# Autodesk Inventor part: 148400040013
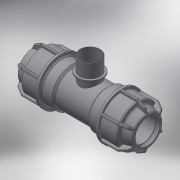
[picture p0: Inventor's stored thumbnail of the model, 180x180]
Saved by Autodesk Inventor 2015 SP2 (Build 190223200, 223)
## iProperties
Created: 2017-08
Part Number: 148400040013
Material: Generic
Description: PLASSON L.14 TEE MALE ADAPTOR (SILVER) 40-1.1/4"-40
Document SubType Name: Modeling
Designer: KIM
Density: 1 g/cm^3
Appearance: Default
Author: KIM
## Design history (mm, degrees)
derived "148400.ipt"
feature "Solid1::148400.ipt"
feature "Solid2::148400.ipt"
tag "TaggingFeature1"
body "Solid1"
body "Solid2"
other parameters: "d2" = 62, "d4" = 15 deg, "d5" = 40.92, "d6" = 13.5036, "d10" = 73, "d16" = 40.8, "d17" = 3.1, "d22" = 64, "d24" = 3.1, "d25" = 65.7, "d26" = 54.75, "d27" = 3.1, "d28" = 135 deg, "d29" = 1.86, "d31" = 2, "d46" = 150 deg, "d49" = 3.65, "d50" = 0, "d58" = 1.2, "d61" = 360 deg, "d63" = 36, "d64" = 86.5, "d80" = 57.6, "d81" = 3.2, "d84" = 3.1, "d94" = 68, "d96" = 41.91, "d108" = 1.2, "d111" = 0, "d113" = 36, "d114" = 50.292, "d115" = 22, "d116" = 2.2, "d117" = 41.91, "R_" = 41.91, "E_" = 73, "H_" = 173, "l_" = 62, "l_2" = 22, "A_" = 68
